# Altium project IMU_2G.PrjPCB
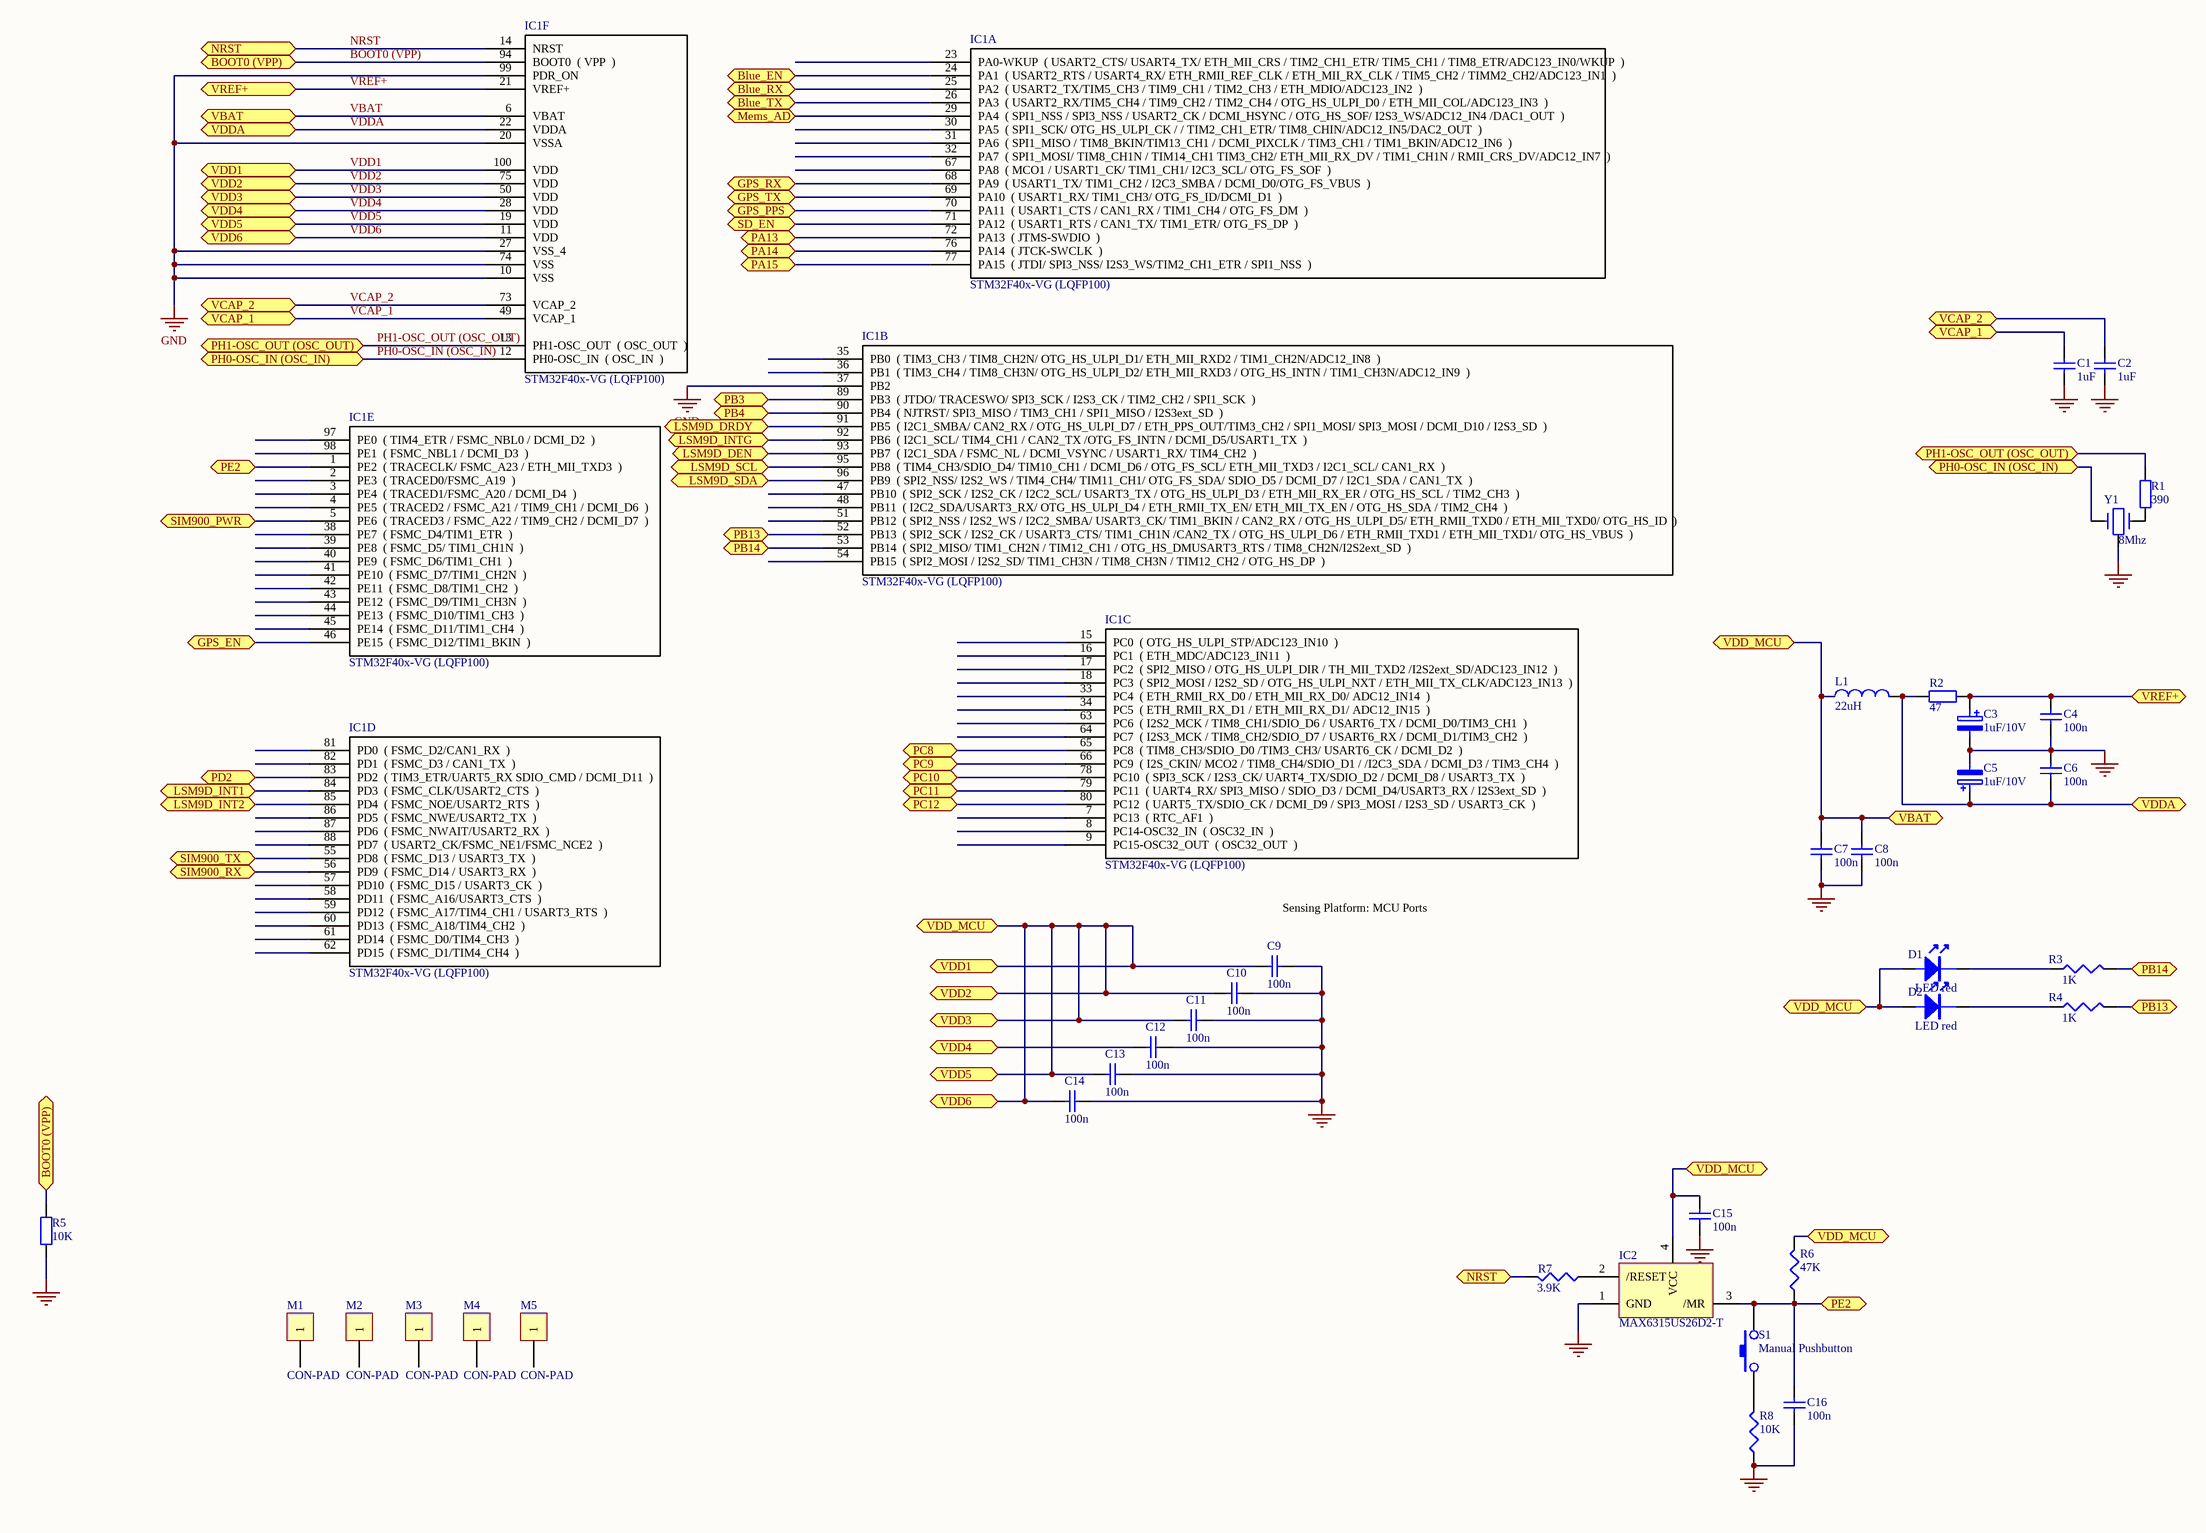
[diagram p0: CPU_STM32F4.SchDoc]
4 sheets, 91 parts. Net scope: flat (ports and power ports of the same name join across sheets).
Board file: IMU_AUDIO.PcbDoc
Sheets:
  CPU_STM32F4.SchDoc
  IMU_module.SchDoc
  IMU_POW.SchDoc
  IMU_SD.SchDoc

## Sheet CPU_STM32F4.SchDoc
size A2

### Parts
C1  1uF  [0603]
C2  1uF  [0603]
C3  1uF/10V  [C-0805]
C4  100n  [0603]
C5  1uF/10V  [C-0805]
C6  100n  [0603]
C7  100n  [0603]
C8  100n  [0603]
C9  100n  [0603]
C10  100n  [0603]
C11  100n  [0603]
C12  100n  [0603]
C13  100n  [0603]
C14  100n  [0603]
C15  100n  [0603]
C16  100n  [0603]
D1  LED red  [D0805]
D2  LED red  [D0805]
IC1  STM32F40x-VG (LQFP100)  [LQFP100 (14*14)]  (parts A,B,C,D,E,F of 6)
IC2  MAX6315US26D2-T  [TO-253]
L1  22uH  [0603]
M1  CON-PAD  [BAD_MARK]
M2  CON-PAD  [BAD_MARK]
M3  CON-PAD  [BAD_MARK]
M4  CON-PAD  [BAD_MARK]
M5  CON-PAD  [BAD_MARK]
R1  390  [0603]
R2  47  [0603]
R3  1K  [0603]
R4  1K  [0603]
R5  10K  [0603]
R6  47K  [0603]
R7  3.9K  [0603]
R8  10K  [0603]
S1  Manual Pushbutton  [KEY-6*4]
Y1  8Mhz  [XT-3.2*1.5]

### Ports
Blue_EN, Blue_RX, Blue_TX, BOOT0 (VPP), GPS_EN, GPS_PPS, GPS_RX, GPS_TX, LSM9D_DEN, LSM9D_DRDY, LSM9D_INT1, LSM9D_INT2, LSM9D_INTG, LSM9D_SCL, LSM9D_SDA, Mems_AD, NRST, PA13, PA14, PA15, PB3, PB4, PB13, PB14, PC8, PC9, PC10, PC11, PC12, PD2, PE2, PH0-OSC_IN (OSC_IN), PH1-OSC_OUT (OSC_OUT), SD_EN, SIM900_PWR, SIM900_RX, SIM900_TX, VBAT, VCAP_1, VCAP_2, VDD1, VDD2, VDD3, VDD4, VDD5, VDD6, VDD_MCU, VDDA, VREF+

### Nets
GND: C1.1 C2.1 C3.2 C4.1 C5.2 C6.2 C7.1 C8.1 C9.2 C10.2 C11.2 C12.2 C13.2 C14.2 C15.2 C16.2 IC1.10(VSS) IC1.20(VSSA) IC1.27(VSS_4) IC1.37(PB2) IC1.74(VSS) IC1.99(PDR_ON) IC2.1(GND) R5.1 R8.1 Y1.2
BOOT0 (VPP): IC1.94(BOOT0__(_VPP__)) R5.2 ; port BOOT0 (VPP)
NRST: IC1.14(NRST) R7.2 ; port NRST
PH0-OSC_IN (OSC_IN): IC1.12(PH0-OSC_IN__(_OSC_IN__)) Y1.1 ; port PH0-OSC_IN (OSC_IN)
PH1-OSC_OUT (OSC_OUT): IC1.13(PH1-OSC_OUT__(_OSC_OUT__)) R1.2 ; port PH1-OSC_OUT (OSC_OUT)
VBAT: C7.2 C8.2 C9.1 C10.1 C11.1 C13.1 C14.1 C15.1 D1.A D2.A IC1.6(VBAT) IC1.11(VDD) IC1.19(VDD) IC1.50(VDD) IC1.75(VDD) IC1.100(VDD) IC2.4(VCC) L1.1 R6.2 ; port VBAT, port VDD1, port VDD2, port VDD3, port VDD5, port VDD6, port VDD_MCU  [also labelled VDD1, VDD2, VDD3, VDD5, VDD6]
VCAP_1: C1.2 IC1.49(VCAP_1) ; port VCAP_1
VCAP_2: C2.2 IC1.73(VCAP_2) ; port VCAP_2
VDD4: C12.1 IC1.28(VDD) ; port VDD4
VDDA: C5.1 C6.1 IC1.22(VDDA) L1.2 R2.1 ; port VDDA
VREF+: C3.1 C4.2 IC1.21(VREF+) R2.2 ; port VREF+
NetC16_1: C16.1 IC1.1(PE2__(_TRACECLK/_FSMC_A23_/_ETH_MII_TXD3__)) IC2.3(/MR) R6.1 S1.2 ; port PE2
NetD1_K: D1.K R3.1
NetD2_K: D2.K R4.1
NetESD1_1: IC1.78(PC10__(_SPI3_SCK_/_I2S3_CK/_UART4_TX/SDIO_D2_/_DCMI_D8_/_USART3_TX__)) ; port PC10
NetESD1_2: IC1.79(PC11__(_UART4_RX/_SPI3_MISO_/_SDIO_D3_/_DCMI_D4/USART3_RX_/_I2S3ext_SD__)) ; port PC11
NetESD1_3: IC1.80(PC12__(_UART5_TX/SDIO_CK_/_DCMI_D9_/_SPI3_MOSI_/_I2S3_SD_/_USART3_CK__)) ; port PC12
NetESD1_4: IC1.83(PD2__(_TIM3_ETR/UART5_RX_SDIO_CMD_/_DCMI_D11__)) ; port PD2
NetESD1_5: IC1.65(PC8__(_TIM8_CH3/SDIO_D0_/TIM3_CH3/_USART6_CK_/_DCMI_D2__)) ; port PC8
NetESD1_8: IC1.66(PC9__(_I2S_CKIN/_MCO2_/_TIM8_CH4/SDIO_D1_/_/I2C3_SDA_/_DCMI_D3_/_TIM3_CH4__)) ; port PC9
NetGPRS_5: IC1.5(PE6__(_TRACED3_/_FSMC_A22_/_TIM9_CH2_/_DCMI_D7__)) ; port SIM900_PWR
NetGPRS_6: IC1.56(PD9__(_FSMC_D14_/_USART3_RX__)) ; port SIM900_RX
NetGPRS_8: IC1.55(PD8__(_FSMC_D13_/_USART3_TX__)) ; port SIM900_TX
NetIC1_24: IC1.24(PA1__(_USART2_RTS_/_USART4_RX/_ETH_RMII_REF_CLK_/_ETH_MII_RX_CLK_/_TIM5_CH2_/_TIMM2_CH2/ADC123_IN1__)) ; port Blue_EN
NetIC1_25: IC1.25(PA2__(_USART2_TX/TIM5_CH3_/_TIM9_CH1_/_TIM2_CH3_/_ETH_MDIO/ADC123_IN2__)) ; port Blue_RX
NetIC1_26: IC1.26(PA3__(_USART2_RX/TIM5_CH4_/_TIM9_CH2_/_TIM2_CH4_/_OTG_HS_ULPI_D0_/_ETH_MII_COL/ADC123_IN3__)) ; port Blue_TX
NetIC1_29: IC1.29(PA4__(_SPI1_NSS_/_SPI3_NSS_/_USART2_CK_/_DCMI_HSYNC_/_OTG_HS_SOF/_I2S3_WS/ADC12_IN4_/DAC1_OUT__)) ; port Mems_AD
NetIC1_46: IC1.46(PE15__(_FSMC_D12/TIM1_BKIN__)) ; port GPS_EN
NetIC1_52: IC1.52(PB13__(_SPI2_SCK_/_I2S2_CK_/_USART3_CTS/_TIM1_CH1N_/CAN2_TX_/_OTG_HS_ULPI_D6_/_ETH_RMII_TXD1_/_ETH_MII_TXD1/_OTG_HS_VBUS__)) R4.2 ; port PB13
NetIC1_53: IC1.53(PB14__(_SPI2_MISO/_TIM1_CH2N_/_TIM12_CH1_/_OTG_HS_DMUSART3_RTS_/_TIM8_CH2N/I2S2ext_SD__)) R3.2 ; port PB14
NetIC1_68: IC1.68(PA9__(_USART1_TX/_TIM1_CH2_/_I2C3_SMBA_/_DCMI_D0/OTG_FS_VBUS__)) ; port GPS_RX
NetIC1_69: IC1.69(PA10__(_USART1_RX/_TIM1_CH3/_OTG_FS_ID/DCMI_D1__)) ; port GPS_TX
NetIC1_70: IC1.70(PA11__(_USART1_CTS_/_CAN1_RX_/_TIM1_CH4_/_OTG_FS_DM__)) ; port GPS_PPS
NetIC1_71: IC1.71(PA12__(_USART1_RTS_/_CAN1_TX/_TIM1_ETR/_OTG_FS_DP__)) ; port SD_EN
NetIC1_72: IC1.72(PA13__(_JTMS-SWDIO__)) ; port PA13
NetIC1_76: IC1.76(PA14__(_JTCK-SWCLK__)) ; port PA14
NetIC1_77: IC1.77(PA15__(_JTDI/_SPI3_NSS/_I2S3_WS/TIM2_CH1_ETR_/_SPI1_NSS__)) ; port PA15
NetIC1_84: IC1.84(PD3__(_FSMC_CLK/USART2_CTS__)) ; port LSM9D_INT1
NetIC1_85: IC1.85(PD4__(_FSMC_NOE/USART2_RTS__)) ; port LSM9D_INT2
NetIC1_89: IC1.89(PB3__(_JTDO/_TRACESWO/_SPI3_SCK_/_I2S3_CK_/_TIM2_CH2_/_SPI1_SCK__)) ; port PB3
NetIC1_90: IC1.90(PB4__(_NJTRST/_SPI3_MISO_/_TIM3_CH1_/_SPI1_MISO_/_I2S3ext_SD__)) ; port PB4
NetIC1_91: IC1.91(PB5__(_I2C1_SMBA/_CAN2_RX_/_OTG_HS_ULPI_D7_/_ETH_PPS_OUT/TIM3_CH2_/_SPI1_MOSI/_SPI3_MOSI_/_DCMI_D10_/_I2S3_SD__)) ; port LSM9D_DRDY
NetIC1_92: IC1.92(PB6__(_I2C1_SCL/_TIM4_CH1_/_CAN2_TX_/OTG_FS_INTN_/_DCMI_D5/USART1_TX__)) ; port LSM9D_INTG
NetIC1_93: IC1.93(PB7__(_I2C1_SDA_/_FSMC_NL_/_DCMI_VSYNC_/_USART1_RX/_TIM4_CH2__)) ; port LSM9D_DEN
NetIC1_95: IC1.95(PB8__(_TIM4_CH3/SDIO_D4/_TIM10_CH1_/_DCMI_D6_/_OTG_FS_SCL/_ETH_MII_TXD3_/_I2C1_SCL/_CAN1_RX__)) ; port LSM9D_SCL
NetIC1_96: IC1.96(PB9__(_SPI2_NSS/_I2S2_WS_/_TIM4_CH4/_TIM11_CH1/_OTG_FS_SDA/_SDIO_D5_/_DCMI_D7_/_I2C1_SDA_/_CAN1_TX__)) ; port LSM9D_SDA
NetIC2_2: IC2.2(/RESET) R7.1
NetR1_1: R1.1 Y1.3
NetR8_2: R8.2 S1.1

Not connected (* = marked no-connect by the designer): IC1 2(PE3__(_TRACED0/FSMC_A19__)) 3(PE4__(_TRACED1/FSMC_A20_/_DCMI_D4__)) 4(PE5__(_TRACED2_/_FSMC_A21_/_TIM9_CH1_/_DCMI_D6__)) 7(PC13__(_RTC_AF1__)) 8(PC14-OSC32_IN__(_OSC32_IN__)) 9(PC15-OSC32_OUT__(_OSC32_OUT__)) 15(PC0__(_OTG_HS_ULPI_STP/ADC123_IN10__)) 16(PC1__(_ETH_MDC/ADC123_IN11__)) 17(PC2__(_SPI2_MISO_/_OTG_HS_ULPI_DIR_/_TH_MII_TXD2_/I2S2ext_SD/ADC123_IN12__)) 18(PC3__(_SPI2_MOSI_/_I2S2_SD_/_OTG_HS_ULPI_NXT_/_ETH_MII_TX_CLK/ADC123_IN13__)) 23(PA0-WKUP__(_USART2_CTS/_USART4_TX/_ETH_MII_CRS_/_TIM2_CH1_ETR/_TIM5_CH1_/_TIM8_ETR/ADC123_IN0/WKUP__)) 30(PA5__(_SPI1_SCK/_OTG_HS_ULPI_CK_/_/_TIM2_CH1_ETR/_TIM8_CHIN/ADC12_IN5/DAC2_OUT__)) 31(PA6__(_SPI1_MISO_/_TIM8_BKIN/TIM13_CH1_/_DCMI_PIXCLK_/_TIM3_CH1_/_TIM1_BKIN/ADC12_IN6__)) 32(PA7__(_SPI1_MOSI/_TIM8_CH1N_/_TIM14_CH1_TIM3_CH2/_ETH_MII_RX_DV_/_TIM1_CH1N_/_RMII_CRS_DV/ADC12_IN7__)) 33(PC4__(_ETH_RMII_RX_D0_/_ETH_MII_RX_D0/_ADC12_IN14__)) 34(PC5__(_ETH_RMII_RX_D1_/_ETH_MII_RX_D1/_ADC12_IN15__)) 35(PB0__(_TIM3_CH3_/_TIM8_CH2N/_OTG_HS_ULPI_D1/_ETH_MII_RXD2_/_TIM1_CH2N/ADC12_IN8__)) 36(PB1__(_TIM3_CH4_/_TIM8_CH3N/_OTG_HS_ULPI_D2/_ETH_MII_RXD3_/_OTG_HS_INTN_/_TIM1_CH3N/ADC12_IN9__)) 38(PE7__(_FSMC_D4/TIM1_ETR__)) 39(PE8__(_FSMC_D5/_TIM1_CH1N__)) 40(PE9__(_FSMC_D6/TIM1_CH1__)) 41(PE10__(_FSMC_D7/TIM1_CH2N__)) 42(PE11__(_FSMC_D8/TIM1_CH2__)) 43(PE12__(_FSMC_D9/TIM1_CH3N__)) 44(PE13__(_FSMC_D10/TIM1_CH3__)) 45(PE14__(_FSMC_D11/TIM1_CH4__)) 47(PB10__(_SPI2_SCK_/_I2S2_CK_/_I2C2_SCL/_USART3_TX_/_OTG_HS_ULPI_D3_/_ETH_MII_RX_ER_/_OTG_HS_SCL_/_TIM2_CH3__)) 48(PB11__(_I2C2_SDA/USART3_RX/_OTG_HS_ULPI_D4_/_ETH_RMII_TX_EN/_ETH_MII_TX_EN_/_OTG_HS_SDA_/_TIM2_CH4__)) 51(PB12__(_SPI2_NSS_/_I2S2_WS_/_I2C2_SMBA/_USART3_CK/_TIM1_BKIN_/_CAN2_RX_/_OTG_HS_ULPI_D5/_ETH_RMII_TXD0_/_ETH_MII_TXD0/_OTG_HS_ID__)) 54(PB15__(_SPI2_MOSI_/_I2S2_SD/_TIM1_CH3N_/_TIM8_CH3N_/_TIM12_CH2_/_OTG_HS_DP__)) 57(PD10__(_FSMC_D15_/_USART3_CK__)) 58(PD11__(_FSMC_A16/USART3_CTS__)) 59(PD12__(_FSMC_A17/TIM4_CH1_/_USART3_RTS__)) 60(PD13__(_FSMC_A18/TIM4_CH2__)) 61(PD14__(_FSMC_D0/TIM4_CH3__)) 62(PD15__(_FSMC_D1/TIM4_CH4__)) 63(PC6__(_I2S2_MCK_/_TIM8_CH1/SDIO_D6_/_USART6_TX_/_DCMI_D0/TIM3_CH1__)) 64(PC7__(_I2S3_MCK_/_TIM8_CH2/SDIO_D7_/_USART6_RX_/_DCMI_D1/TIM3_CH2__)) 67(PA8__(_MCO1_/_USART1_CK/_TIM1_CH1/_I2C3_SCL/_OTG_FS_SOF__)) 81(PD0__(_FSMC_D2/CAN1_RX__)) 82(PD1__(_FSMC_D3_/_CAN1_TX__)) 86(PD5__(_FSMC_NWE/USART2_TX__)) 87(PD6__(_FSMC_NWAIT/USART2_RX__)) 88(PD7__(_USART2_CK/FSMC_NE1/FSMC_NCE2__)) 97(PE0__(_TIM4_ETR_/_FSMC_NBL0_/_DCMI_D2__)) 98(PE1__(_FSMC_NBL1_/_DCMI_D3__)); M1 1; M2 1; M3 1; M4 1; M5 1

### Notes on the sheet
- (near C9) Sensing Platform: MCU Ports

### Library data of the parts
C1 C2 = Cap: TANTAMOUNT? 595D Vishay Sprague,50V,22.5mOhm; Value: 1u
C3 C5 = C-A(3216-18): 耐压: 10V
C4 C6-C8 C10-C16 = Cap: TANTAMOUNT? 595D Vishay Sprague,50V,22.5mOhm
C9 = Cap: TANTAMOUNT? 595D Vishay Sprague,50V,22.5mOhm; Value: 4.7u
D1 D2 = diode-LED: LED
IC1 = STM32F40x-VG
IC2 = MAX 6468: MAX 6468XS16D3 Reset and Supervisory Circuit
L1 = Inductor: fcm1608-0603; Code_IEC: 1005
R1 R2 R5 = R-0603: 0603(SMD); 功率: 1/10w
R3 R4 R6-R8 = Res3: Resistor
S1 = 微动开关
Y1 = CRYSTAL-X3: 3PIN; 频率: 20MHZ-39.9MHZ

## Sheet IMU_module.SchDoc
size A3
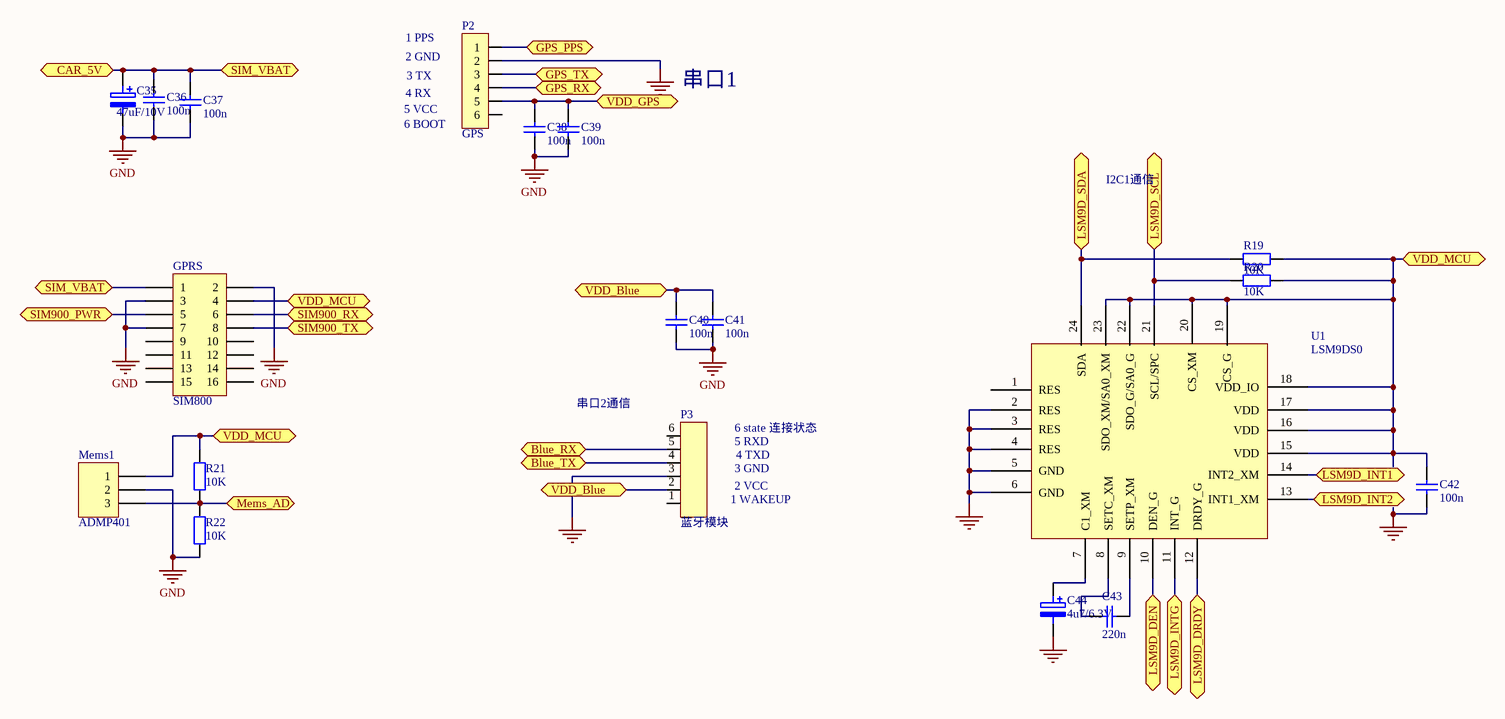
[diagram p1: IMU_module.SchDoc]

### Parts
C35  47uF/10V  [C-A(3216-18)]
C36  100n  [0603]
C37  100n  [0603]
C38  100n  [0603]
C39  100n  [0603]
C40  100n  [0603]
C41  100n  [0603]
C42  100n  [0603]
C43  220n  [0603]
C44  4u7/6.3V  [C-0805]
GPRS  SIM800  [SIM800]
Mems1  ADMP401  [ADMP401]
P2  GPS  [GPS 28*28MM]
P3  蓝牙模块  [HC-06(35.7*15.2MM)]
R19  10K  [0603]
R20  10K  [0603]
R21  10K  [0603]
R22  10K  [0603]
U1  LSM9DS0  [QFN(4*4*0.9)]

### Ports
Blue_RX, Blue_TX, CAR_5V, GPS_PPS, GPS_RX, GPS_TX, LSM9D_DEN, LSM9D_DRDY, LSM9D_INT1, LSM9D_INT2, LSM9D_INTG, LSM9D_SCL, LSM9D_SDA, Mems_AD, SIM900_PWR, SIM900_RX, SIM900_TX, SIM_VBAT, VDD_Blue, VDD_GPS, VDD_MCU

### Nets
GND: C35.2 C36.1 C37.1 C38.1 C39.1 C40.1 C41.1 C42.1 C44.2 GPRS.2 GPRS.3 GPRS.7 Mems1.2 P2.2 P3.3 R22.1 U1.2(RES) U1.3(RES) U1.4(RES) U1.5(GND) U1.6(GND)
VBAT: C42.2 GPRS.4 Mems1.1 R19.2 R20.2 R21.2 U1.15(VDD) U1.16(VDD) U1.17(VDD) U1.18(VDD_IO) U1.19(CS_G) U1.20(CS_XM) U1.22(SDO_G/SA0_G) U1.23(SDO_XM/SA0_XM) ; port VDD_MCU
NetC18_2: C35.1 C36.2 C37.2 GPRS.1 ; port CAR_5V, port SIM_VBAT
NetC20_1: C40.2 C41.2 P3.2 ; port VDD_Blue
NetC27_1: C38.2 C39.2 P2.5 ; port VDD_GPS
NetC43_1: C43.1 U1.9(SETP_XM)
NetC43_2: C43.2 U1.8(SETC_XM)
NetC44_1: C44.1 U1.7(C1_XM)
NetGPRS_5: GPRS.5 ; port SIM900_PWR
NetGPRS_6: GPRS.6 ; port SIM900_RX
NetGPRS_8: GPRS.8 ; port SIM900_TX
NetIC1_25: P3.5 ; port Blue_RX
NetIC1_26: P3.4 ; port Blue_TX
NetIC1_29: Mems1.3 R21.1 R22.2 ; port Mems_AD
NetIC1_68: P2.4 ; port GPS_RX
NetIC1_69: P2.3 ; port GPS_TX
NetIC1_70: P2.1 ; port GPS_PPS
NetIC1_84: U1.14(INT2_XM) ; port LSM9D_INT1
NetIC1_85: U1.13(INT1_XM) ; port LSM9D_INT2
NetIC1_91: U1.12(DRDY_G) ; port LSM9D_DRDY
NetIC1_92: U1.11(INT_G) ; port LSM9D_INTG
NetIC1_93: U1.10(DEN_G) ; port LSM9D_DEN
NetIC1_95: R20.1 U1.21(SCL/SPC) ; port LSM9D_SCL
NetIC1_96: R19.1 U1.24(SDA) ; port LSM9D_SDA

Not connected (* = marked no-connect by the designer): GPRS 9 10 11 12 13 14 15 16; P2 6; P3 1 6; U1 1(RES)

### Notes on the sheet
- (near P2) 1 PPS
- (near P2) 2 GND
- (near P2) 6 BOOT
- 5 VCC
- 4 RX
- 3 TX
- 串口1
- I2C1通信
- 串口2通信
- 6 state 连接状态
- 5 RXD
- 4 TXD
- (near P3) 1 WAKEUP
- 2 VCC
- 3 GND

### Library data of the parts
C35 C44 = C-A(3216-18): 耐压: 10V
C36-C42 = Cap: as C4 on sheet CPU_STM32F4
C43 = Cap: TANTAMOUNT? 595D Vishay Sprague,50V,22.5mOhm; Value: 100n
GPRS = MHDR2X8: Header, 8-Pin, Dual row
Mems1 = MHDR1X3: Header, 3-Pin
P2 = CON6-2.54: (栅)围栏式立(卧)6PIN
P3 = CON-SIP6-2.54: 单排针6PIN
R19-R22 = R-0603: 0603(SMD); 功率: 1/10w

## Sheet IMU_POW.SchDoc
size A3
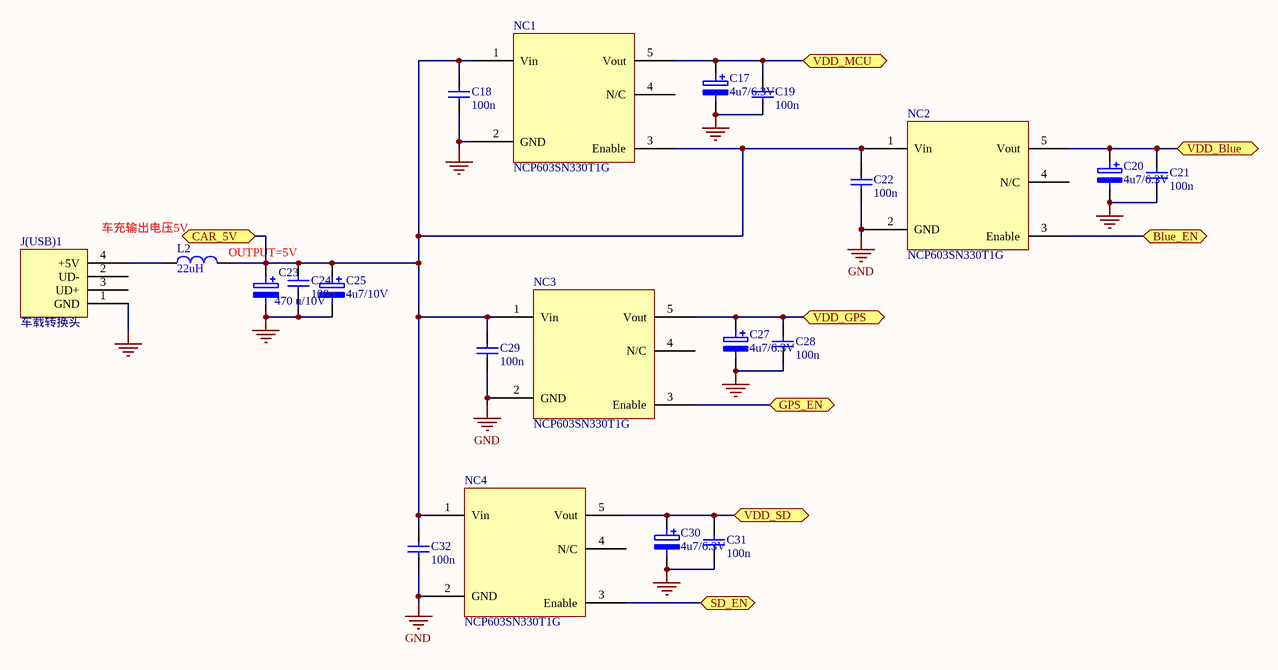
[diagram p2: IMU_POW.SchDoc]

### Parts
C17  4u7/6.3V  [C-0805]
C18  100n  [0603]
C19  100n  [0603]
C20  4u7/6.3V  [C-0805]
C21  100n  [0603]
C22  100n  [0603]
C23  470 u/10V  [C-D(7343-31)]
C24  100n  [0603]
C25  4u7/10V  [C-A(3216-18)]
C27  4u7/6.3V  [C-0805]
C28  100n  [0603]
C29  100n  [0603]
C30  4u7/6.3V  [C-0805]
C31  100n  [0603]
C32  100n  [0603]
J(USB)1  车载转换头  [USB-SMT]
L2  22uH  [0805]
NC1  NCP603SN330T1G  [TSSOP-5]
NC2  NCP603SN330T1G  [TSSOP-5]
NC3  NCP603SN330T1G  [TSSOP-5]
NC4  NCP603SN330T1G  [TSSOP-5]

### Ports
Blue_EN, CAR_5V, GPS_EN, SD_EN, VDD_Blue, VDD_GPS, VDD_MCU, VDD_SD

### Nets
GND: C17.2 C18.1 C19.1 C20.2 C21.1 C22.1 C23.2 C24.1 C25.2 C27.2 C28.1 C29.1 C30.2 C31.1 C32.1 J(USB)1.1(GND) NC1.2(GND) NC2.2(GND) NC3.2(GND) NC4.2(GND)
VBAT: C17.1 C19.2 NC1.5(Vout) ; port VDD_MCU
NetC18_2: C18.2 C22.2 C23.1 C24.2 C25.1 C29.2 C32.2 L2.2 NC1.1(Vin) NC1.3(Enable) NC2.1(Vin) NC3.1(Vin) NC4.1(Vin) ; port CAR_5V
NetC20_1: C20.1 C21.2 NC2.5(Vout) ; port VDD_Blue
NetC27_1: C27.1 C28.2 NC3.5(Vout) ; port VDD_GPS
NetC30_1: C30.1 C31.2 NC4.5(Vout) ; port VDD_SD
NetIC1_24: NC2.3(Enable) ; port Blue_EN
NetIC1_46: NC3.3(Enable) ; port GPS_EN
NetIC1_71: NC4.3(Enable) ; port SD_EN
NetJ(USB)1_4: J(USB)1.4(+5V) L2.1

Not connected (* = marked no-connect by the designer): J(USB)1 2(UD-) 3(UD+); NC1 4(N/C); NC2 4(N/C); NC3 4(N/C); NC4 4(N/C)

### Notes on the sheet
- 车充输出电压5V
- OUTPUT=5V

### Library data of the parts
C17 C20 C25 C27 C30 = C-A(3216-18): 耐压: 10V
C18 C19 C21 C22 C24 C28 C29 C31 C32 = Cap: as C4 on sheet CPU_STM32F4
C23 = C-RB.1
J(USB)1 = CON-USB1: USB
L2 = INDUCTOR
NC1-NC4 = NCP551

## Sheet IMU_SD.SchDoc
size A4
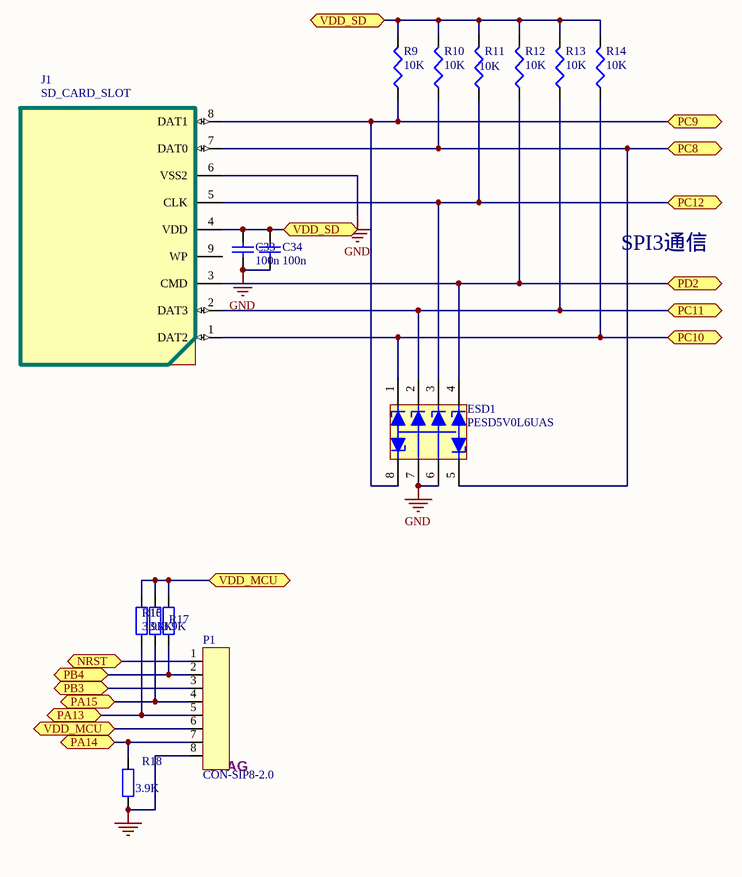
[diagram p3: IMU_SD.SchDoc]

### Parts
C33  100n  [0603]
C34  100n  [0603]
ESD1  PESD5V0L6UAS  [MSOP-8]
J1  SD_CARD_SLOT  [mini-SD]
P1  CON-SIP8-2.0  [PLUG1.27-8P]
R9  10K  [0603]
R10  10K  [0603]
R11  10K  [0603]
R12  10K  [0603]
R13  10K  [0603]
R14  10K  [0603]
R15  3.9K  [0603]
R16  3.9K  [0603]
R17  3.9K  [0603]
R18  3.9K  [0603]

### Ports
NRST, PA13, PA14, PA15, PB3, PB4, PC8, PC9, PC10, PC11, PC12, PD2, VDD_MCU, VDD_SD

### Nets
GND: C33.2 C34.2 ESD1.6 ESD1.7 J1.6(VSS2) P1.8 R18.1
NRST: P1.1 ; port NRST
VBAT: P1.6 R15.2 R16.2 R17.2 ; port VDD_MCU
NetC30_1: C33.1 C34.1 J1.4(VDD) R9.2 R10.2 R11.2 R12.2 R13.2 R14.2 ; port VDD_SD
NetESD1_1: ESD1.1 J1.1(DAT2) R14.1 ; port PC10
NetESD1_2: ESD1.2 J1.2(DAT3) R13.1 ; port PC11
NetESD1_3: ESD1.3 J1.5(CLK) R11.1 ; port PC12
NetESD1_4: ESD1.4 J1.3(CMD) R12.1 ; port PD2
NetESD1_5: ESD1.5 J1.7(DAT0) R10.1 ; port PC8
NetESD1_8: ESD1.8 J1.8(DAT1) R9.1 ; port PC9
NetIC1_72: P1.5 R16.1 ; port PA13
NetIC1_76: P1.7 R18.2 ; port PA14
NetIC1_77: P1.4 R15.1 ; port PA15
NetIC1_89: P1.3 ; port PB3
NetIC1_90: P1.2 R17.1 ; port PB4

Not connected (* = marked no-connect by the designer): J1 9(WP)

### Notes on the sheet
- SPI3通信
- (near P1) JTAG

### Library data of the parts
C33 C34 = Cap: Capacitor
ESD1 = PESD5V0L6U
P1 = CON-SIP8-2.0: 单排针8PIN
R9-R14 = Res3: Resistor
R15-R18 = R-0805: 0805(SMD); 功率: 1/8w

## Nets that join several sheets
GND: CPU_STM32F4 (26 pins), IMU_module (21 pins), IMU_POW (20 pins), IMU_SD (7 pins)
NetC18_2: IMU_module (C35.1 C36.2 C37.2 GPRS.1), IMU_POW (13 pins)
NetC20_1: IMU_module (C40.2 C41.2 P3.2), IMU_POW (C20.1 C21.2 NC2.5)
NetC27_1: IMU_module (C38.2 C39.2 P2.5), IMU_POW (C27.1 C28.2 NC3.5)
NetC30_1: IMU_POW (C30.1 C31.2 NC4.5), IMU_SD (9 pins)
NetESD1_1: CPU_STM32F4 (IC1.78), IMU_SD (ESD1.1 J1.1 R14.1)
NetESD1_2: CPU_STM32F4 (IC1.79), IMU_SD (ESD1.2 J1.2 R13.1)
NetESD1_3: CPU_STM32F4 (IC1.80), IMU_SD (ESD1.3 J1.5 R11.1)
NetESD1_4: CPU_STM32F4 (IC1.83), IMU_SD (ESD1.4 J1.3 R12.1)
NetESD1_5: CPU_STM32F4 (IC1.65), IMU_SD (ESD1.5 J1.7 R10.1)
NetESD1_8: CPU_STM32F4 (IC1.66), IMU_SD (ESD1.8 J1.8 R9.1)
NetGPRS_5: CPU_STM32F4 (IC1.5), IMU_module (GPRS.5)
NetGPRS_6: CPU_STM32F4 (IC1.56), IMU_module (GPRS.6)
NetGPRS_8: CPU_STM32F4 (IC1.55), IMU_module (GPRS.8)
NetIC1_24: CPU_STM32F4 (IC1.24), IMU_POW (NC2.3)
NetIC1_25: CPU_STM32F4 (IC1.25), IMU_module (P3.5)
NetIC1_26: CPU_STM32F4 (IC1.26), IMU_module (P3.4)
NetIC1_29: CPU_STM32F4 (IC1.29), IMU_module (Mems1.3 R21.1 R22.2)
NetIC1_46: CPU_STM32F4 (IC1.46), IMU_POW (NC3.3)
NetIC1_68: CPU_STM32F4 (IC1.68), IMU_module (P2.4)
NetIC1_69: CPU_STM32F4 (IC1.69), IMU_module (P2.3)
NetIC1_70: CPU_STM32F4 (IC1.70), IMU_module (P2.1)
NetIC1_71: CPU_STM32F4 (IC1.71), IMU_POW (NC4.3)
NetIC1_72: CPU_STM32F4 (IC1.72), IMU_SD (P1.5 R16.1)
NetIC1_76: CPU_STM32F4 (IC1.76), IMU_SD (P1.7 R18.2)
NetIC1_77: CPU_STM32F4 (IC1.77), IMU_SD (P1.4 R15.1)
NetIC1_84: CPU_STM32F4 (IC1.84), IMU_module (U1.14)
NetIC1_85: CPU_STM32F4 (IC1.85), IMU_module (U1.13)
NetIC1_89: CPU_STM32F4 (IC1.89), IMU_SD (P1.3)
NetIC1_90: CPU_STM32F4 (IC1.90), IMU_SD (P1.2 R17.1)
NetIC1_91: CPU_STM32F4 (IC1.91), IMU_module (U1.12)
NetIC1_92: CPU_STM32F4 (IC1.92), IMU_module (U1.11)
NetIC1_93: CPU_STM32F4 (IC1.93), IMU_module (U1.10)
NetIC1_95: CPU_STM32F4 (IC1.95), IMU_module (R20.1 U1.21)
NetIC1_96: CPU_STM32F4 (IC1.96), IMU_module (R19.1 U1.24)
NRST: CPU_STM32F4 (IC1.14 R7.2), IMU_SD (P1.1)
VBAT: CPU_STM32F4 (19 pins), IMU_module (14 pins), IMU_POW (C17.1 C19.2 NC1.5), IMU_SD (P1.6 R15.2 R16.2 R17.2)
